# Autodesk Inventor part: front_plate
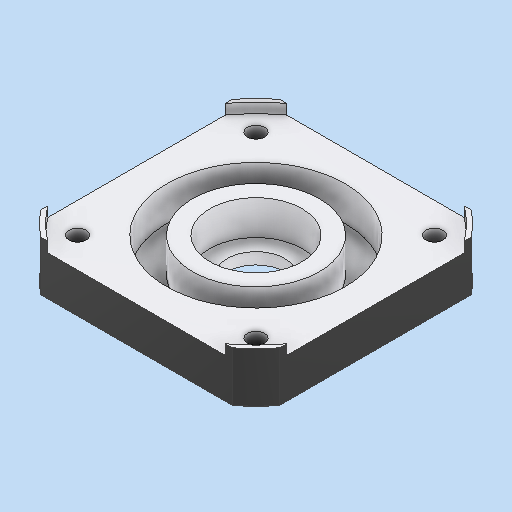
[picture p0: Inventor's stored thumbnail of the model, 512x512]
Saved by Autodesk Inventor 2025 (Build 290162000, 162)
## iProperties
Created: 2025-05
Part Number: front_plate
Material: Generico
Description: front_plate
Document SubType Name: Modeling
Designer: R5800u
Density: 1 g/cm^3
Appearance: Default
Author: R5800u
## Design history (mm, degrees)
feature "Base1"
node "Solido1"
